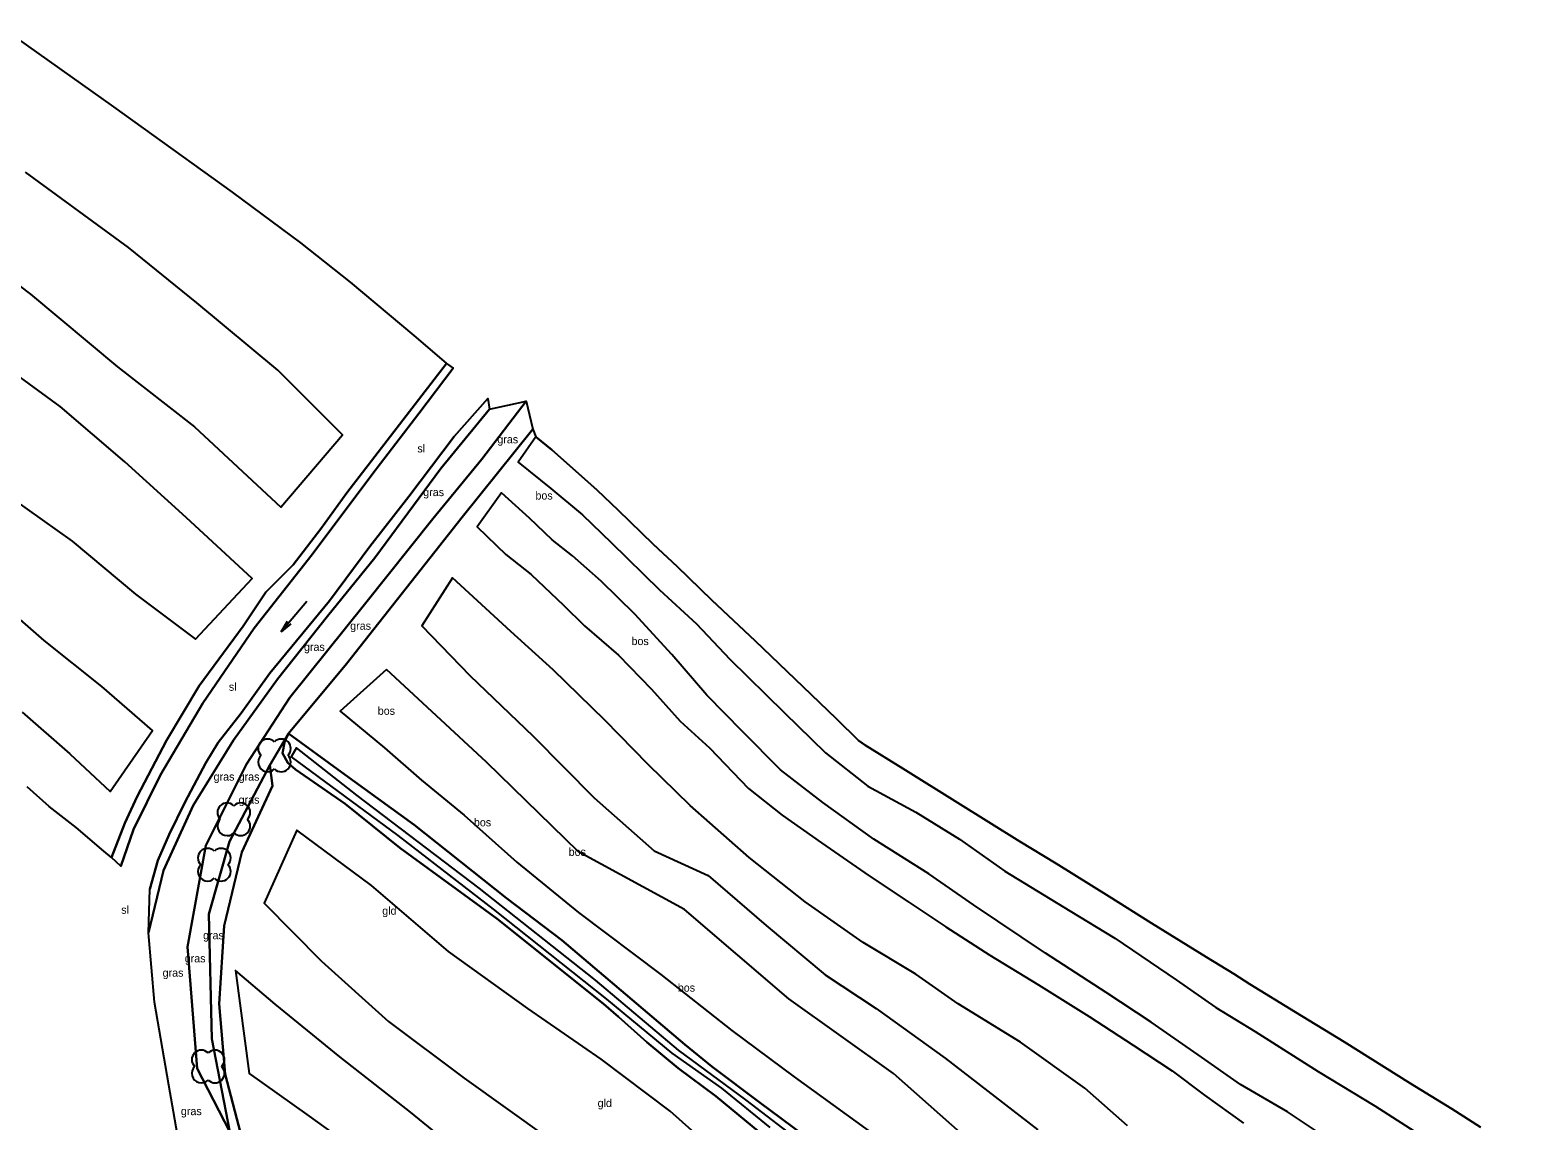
# Model space of a CAD drawing. Extents: x 154825 to 158680, y 370717 to 378075.
# Drawn here: x 155652.5 to 155841.2, y 377079.3 to 377215.8 of the extents above; entities that cross this region are included whole.
import ezdxf

# ---------------------------------------------------------------- set-up
doc = ezdxf.new("R2010")
doc.units = 0
for name, color, linetype in [('boom', 7, 'Continuous'), ('bos(vs)', 7, 'Continuous'), ('breuklijn', 7, 'Continuous'), ('grasland_productiegrasl(vs)', 7, 'Continuous'), ('grazige vegetatie(vs)', 7, 'Continuous'), ('hoogteverschillijn', 7, 'Continuous'), ('insteek sloot', 7, 'Continuous'), ('Sloot bodem', 7, 'Continuous'), ('sloot(vs)', 7, 'Continuous'), ('stroomrichting  watergangen', 7, 'Continuous'), ('vlak_Bos', 7, 'Continuous'), ('vlak_Grasland', 7, 'Continuous'), ('vlak_Grazige_vegetatie', 7, 'Continuous')]:
    doc.layers.add(name, color=color, linetype=linetype)

msp = doc.modelspace()

# ---------------------------------------------------------------- linework, layer by layer
at = {"layer": 'boom'}
for centre, start, end in [((155682.24, 377125.87), 45, 225), ((155683.93, 377125.87), 315, 135), ((155682.24, 377124.17), 134.7431, 315), ((155683.93, 377124.17), 225, 45), ((155677.15, 377117.87), 45, 225), ((155678.85, 377117.87), 315, 135), ((155677.15, 377116.17), 134.7431, 315), ((155678.85, 377116.17), 225, 45), ((155674.71, 377112.18), 45, 225), ((155676.41, 377112.18), 315, 135), ((155674.71, 377110.48), 134.7431, 315), ((155676.41, 377110.48), 225, 45), ((155673.94, 377086.92), 45, 225), ((155675.64, 377086.92), 315, 135), ((155673.94, 377085.22), 134.7431, 315), ((155675.64, 377085.22), 225, 45)]:
    msp.add_arc(centre, 1.2, start, end, dxfattribs=at)
at = {"layer": 'bos(vs)'}
msp.add_lwpolyline([(155715.41, 377165.87), (155706.56, 377154.84), (155692.09, 377136.49), (155684.83, 377127.76)], dxfattribs=at)
at = {"layer": 'breuklijn'}
for points in [[(155714.59, 377169.36), (155709.02, 377162.12), (155702.88, 377154.62), (155694.37, 377143.93), (155685.02, 377132.25), (155679.59, 377123.93), (155674.49, 377113.75), (155672.2, 377101.06), (155673.4, 377085.82), (155677.48, 377077.9), (155675.24, 377089.52), (155674.86, 377105.15), (155677.45, 377114.22), (155682.5, 377123.78), (155682.83, 377121.22), (155679.02, 377112.91), (155676.78, 377103.66), (155676.15, 377093.9), (155676.92, 377085.09), (155679.08, 377076.81), (155677.91, 377076.45), (155677.48, 377077.9)], [(155833.53, 377024.24), (155818.9, 377036.91), (155805.68, 377046.23), (155791.49, 377059.51), (155778.9, 377067.29), (155770.76, 377076.15), (155760.52, 377085.18), (155747.44, 377094.53), (155734.38, 377105.71), (155721.14, 377112.94), (155709.6, 377124.17), (155697.1, 377135.78)]]:
    msp.add_lwpolyline(points, dxfattribs=at)
at = {"layer": 'hoogteverschillijn'}
for points in [[(155649.44, 377215.82), (155662.95, 377206.22), (155677.8, 377195.53), (155686.33, 377189.18), (155692.57, 377184.26), (155700.52, 377177.59), (155703.68, 377174.88)], [(155642.36, 377190.48), (155652.55, 377182.75), (155663.43, 377173.66), (155673.07, 377166.17), (155683.88, 377156.09), (155691.59, 377165.16), (155683.5, 377173.26), (155673.39, 377181.66), (155664.84, 377188.62), (155651.94, 377198.03)], [(155646.49, 377159.86), (155657.77, 377151.84), (155665.7, 377145.19), (155673.21, 377139.57), (155680.3, 377147.18), (155672.02, 377154.79), (155664.37, 377161.78), (155656.28, 377168.7), (155646.77, 377175.61)], [(155833.99, 377078.46), (155830.39, 377080.78), (155825.24, 377083.94), (155816.92, 377089.14), (155810.84, 377092.89), (155805.14, 377096.38), (155803.12, 377097.65), (155799.69, 377099.76), (155792.8, 377104.02), (155787.53, 377107.35), (155780.9, 377111.48), (155776.35, 377114.22), (155768.57, 377119.07), (155761.69, 377123.38), (155757, 377126.28), (155756.17, 377126.9), (155753.42, 377129.58), (155750.23, 377132.65), (155743.24, 377139.35), (155737.8, 377144.46), (155733.47, 377148.66), (155730.46, 377151.47), (155726.09, 377155.72), (155723.46, 377158.24), (155721.49, 377159.97), (155717.77, 377163.27), (155715.77, 377164.92), (155713.56, 377161.74), (155717.66, 377158.43), (155721.61, 377155.14), (155725.23, 377151.67), (155731.24, 377145.76), (155735.9, 377141.51), (155740.07, 377137.08), (155746.86, 377130.4), (155752.03, 377125.32), (155757.34, 377121.15), (155763.35, 377117.93), (155768.81, 377114.52), (155774.47, 377110.52), (155782.61, 377105.57), (155788.23, 377102.13), (155795.92, 377096.91), (155800.89, 377093.47), (155805.78, 377090.47), (155813.67, 377085.46), (155820.75, 377081.15), (155831.25, 377074.41)], [(155815.73, 377076.48), (155809.85, 377080.39), (155803.94, 377083.81), (155798.65, 377087.52), (155792.77, 377091.64), (155787.15, 377095.34), (155779.55, 377100.24), (155770.55, 377106.33), (155764.96, 377110.17), (155758.09, 377114.55), (155751.7, 377119.14), (155746.42, 377123.21), (155741.65, 377128.01), (155737.17, 377132.55), (155732.8, 377137.63), (155728.18, 377142.69), (155723.96, 377146.82), (155720.36, 377149.99), (155717.82, 377152.01), (155714.99, 377154.7), (155711.48, 377157.91), (155708.44, 377153.62), (155712.02, 377150.16), (155715.2, 377147.65), (155719.24, 377143.84), (155721.87, 377141.23), (155726.14, 377137.58), (155730.28, 377133.3), (155733.84, 377129.32), (155737.5, 377125.98), (155742.41, 377120.88), (155746.61, 377117.54), (155751.51, 377114.09), (155757.51, 377109.93), (155762.44, 377106.66), (155767.08, 377103.55), (155772.6, 377100.02), (155778.68, 377096.28), (155785.02, 377092.33), (155790.54, 377088.74), (155795.4, 377085.54), (155799.45, 377082.46), (155804.35, 377078.99)], [(155789.83, 377078.64), (155784.46, 377083.35), (155776.45, 377089.11), (155768.62, 377093.93), (155763.34, 377097.63), (155756.75, 377101.6), (155749.49, 377106.7), (155742.46, 377112.22), (155735.08, 377118.75), (155729.84, 377123.88), (155724.44, 377129.41), (155717.97, 377135.73), (155712.64, 377140.53), (155705.35, 377147.23), (155701.53, 377141.26), (155707.52, 377135.02), (155715.46, 377127.42), (155723.07, 377119.71), (155730.61, 377113.09), (155737.33, 377109.97), (155744.61, 377103.72), (155751.97, 377097.55), (155758.36, 377093.33), (155767.02, 377087.11), (155778.59, 377078.15)], [(155651.5, 377130.43), (155657.47, 377125.21), (155662.52, 377120.48), (155667.82, 377128.14), (155661.5, 377133.63), (155654.29, 377139.41), (155647.2, 377145.56)], [(155697.1, 377135.78), (155691.31, 377130.54), (155696.85, 377125.96), (155701.48, 377121.9), (155706.84, 377117.55), (155713.41, 377111.67), (155721.11, 377105.34), (155731.41, 377097.58), (155740.31, 377090.57), (155748.11, 377084.79), (155759.45, 377076.54), (155772.71, 377065.49), (155781.66, 377058.32), (155788.1, 377052.22), (155797.13, 377045.23), (155804.7, 377040.21), (155814.37, 377032.18), (155822.07, 377026.41), (155831.61, 377016.98), (155841.16, 377008.6)], [(155682.5, 377123.78), (155684.83, 377127.76)], [(155661.72, 377113.02), (155658.27, 377115.99), (155654.91, 377118.61), (155652.15, 377121.07)], [(155740.69, 377073.24), (155732.59, 377080.46), (155723.95, 377086.98), (155714.79, 377093.34), (155704.87, 377100.45), (155695.24, 377108.72), (155685.89, 377115.66), (155681.78, 377106.52), (155688.95, 377099.27), (155697.36, 377091.7), (155706.8, 377084.6), (155717.38, 377077.05)], [(155706.66, 377075.01), (155700.11, 377080.37), (155691.27, 377087.26), (155683.17, 377093.89), (155678.2, 377098.09), (155679.91, 377085.2), (155687.13, 377080.04), (155694.74, 377074.61)]]:
    msp.add_lwpolyline(points, dxfattribs=at)
at = {"layer": 'insteek sloot'}
for points in [[(155704.61, 377174.07), (155692.15, 377157.89), (155688.88, 377153.4), (155685.44, 377148.89), (155682, 377145.47), (155679.15, 377141.2), (155673.66, 377133.73), (155669.56, 377126.88), (155665.91, 377119.88), (155664.37, 377116.52), (155662.69, 377112.25)], [(155671.54, 377057.59), (155672.81, 377058.51), (155673.53, 377060.04), (155673.33, 377061.8), (155672.11, 377070.82), (155669.88, 377083.72), (155668.09, 377094.12), (155667.33, 377102.79), (155669.21, 377110.61), (155672.91, 377118.73), (155677.96, 377126.92), (155683.47, 377134.58), (155689.74, 377142.43), (155695.64, 377149.76), (155703.91, 377160.95), (155709.97, 377168.36)], [(155744.79, 377077.03), (155738.29, 377082.35), (155733.6, 377085.84), (155729.67, 377089.13), (155726.11, 377092.28), (155724.25, 377093.91), (155710.93, 377104.57), (155698.78, 377113.46), (155691.94, 377118.96), (155685.73, 377123.27), (155684.76, 377124.1), (155684.1, 377125.31), (155684.4, 377126.8), (155684.83, 377127.76)], [(155684.83, 377127.76), (155691.49, 377122.9), (155700.55, 377116.34), (155712.1, 377107.15), (155719.05, 377101.88), (155734.43, 377088.82), (155737.82, 377086.08), (155743.87, 377081.52), (155753.26, 377074.56)]]:
    msp.add_lwpolyline(points, dxfattribs=at)
at = {"layer": 'Sloot bodem'}
for points in [[(155663.85, 377111.13), (155665.45, 377115.73), (155668.83, 377122.6), (155674.11, 377131.55), (155680.55, 377140.93), (155687.79, 377150.19), (155695.41, 377160.32), (155701.14, 377167.83), (155705.44, 377173.49)], [(155709.79, 377169.72), (155705.55, 377164.96), (155699.89, 377157.43), (155695.01, 377151.16), (155689.98, 377144.37), (155682.51, 377135.3), (155678.93, 377130.29), (155676.02, 377126.65), (155674.48, 377124.09), (155671.89, 377119.12), (155669.89, 377115.12), (155668.51, 377111.84), (155667.49, 377108.27)], [(155733.62, 377088.1), (155723.24, 377096.86), (155708.69, 377108.38), (155693.43, 377119.98), (155685.84, 377125.97), (155685.19, 377124.83), (155698.54, 377115), (155710.45, 377105.75), (155724.61, 377094.49), (155732.82, 377087.72), (155739, 377083.37), (155745.07, 377078.42)], [(155749.38, 377076.31), (155742.05, 377081.91), (155733.62, 377088.1)]]:
    msp.add_lwpolyline(points, dxfattribs=at)
at = {"layer": 'stroomrichting  watergangen'}
for p, q in [((155687.13, 377144.29), (155683.93, 377140.47)), ((155683.93, 377140.47), (155684.71, 377141.83)), ((155683.95, 377140.47), (155685.16, 377141.49))]:
    msp.add_line(p, q, dxfattribs=at)
at = {"layer": 'vlak_Bos'}
msp.add_lwpolyline([(155753.26, 377074.56), (155743.87, 377081.52), (155737.82, 377086.08), (155734.43, 377088.82), (155719.05, 377101.88), (155712.1, 377107.15), (155700.55, 377116.34), (155691.49, 377122.9), (155684.83, 377127.76), (155692.09, 377136.49), (155706.56, 377154.84), (155715.41, 377165.87), (155715.77, 377164.92), (155717.77, 377163.27), (155721.49, 377159.97), (155723.46, 377158.24), (155726.09, 377155.72), (155730.46, 377151.47), (155733.47, 377148.66), (155737.8, 377144.46), (155743.24, 377139.35), (155750.23, 377132.65), (155753.42, 377129.58), (155756.17, 377126.9), (155757, 377126.28), (155761.69, 377123.38), (155768.57, 377119.07), (155776.35, 377114.22), (155780.9, 377111.48), (155787.53, 377107.35), (155792.8, 377104.02), (155799.69, 377099.76), (155803.12, 377097.65), (155805.14, 377096.38), (155810.84, 377092.89), (155816.92, 377089.14), (155825.24, 377083.94), (155830.39, 377080.78), (155833.99, 377078.46)], dxfattribs=at)
at = {"layer": 'vlak_Grasland'}
for points in [[(155649.44, 377215.82), (155662.95, 377206.22), (155677.8, 377195.53), (155686.33, 377189.18), (155692.57, 377184.26), (155700.52, 377177.59), (155703.68, 377174.88), (155704.61, 377174.07), (155692.15, 377157.89), (155688.88, 377153.4), (155685.44, 377148.89), (155682, 377145.47), (155679.15, 377141.2), (155673.66, 377133.73), (155669.56, 377126.88), (155665.91, 377119.88), (155664.37, 377116.52), (155662.69, 377112.25), (155661.72, 377113.02), (155658.27, 377115.99), (155654.91, 377118.61), (155652.15, 377121.07)], [(155679.08, 377076.81), (155676.92, 377085.09), (155676.15, 377093.9), (155676.78, 377103.66), (155679.02, 377112.91), (155682.83, 377121.22), (155682.5, 377123.78), (155684.83, 377127.76), (155684.4, 377126.8), (155684.1, 377125.31), (155684.76, 377124.1), (155685.73, 377123.27), (155691.94, 377118.96), (155698.78, 377113.46), (155710.93, 377104.57), (155724.25, 377093.91), (155726.11, 377092.28), (155729.67, 377089.13), (155733.6, 377085.84), (155738.29, 377082.35), (155744.79, 377077.03)]]:
    msp.add_lwpolyline(points, dxfattribs=at)
at = {"layer": 'vlak_Grazige_vegetatie'}
for points in [[(155665.45, 377115.73), (155663.85, 377111.13), (155662.69, 377112.25), (155664.37, 377116.52), (155665.91, 377119.88), (155669.56, 377126.88), (155673.66, 377133.73), (155679.15, 377141.2), (155682, 377145.47), (155685.44, 377148.89), (155688.88, 377153.4), (155692.15, 377157.89), (155704.61, 377174.07), (155705.44, 377173.49), (155701.14, 377167.83), (155695.41, 377160.32), (155687.79, 377150.19), (155680.55, 377140.93), (155674.11, 377131.55), (155668.83, 377122.6)], [(155669.21, 377110.61), (155667.33, 377102.79), (155667.49, 377108.27), (155668.51, 377111.84), (155669.89, 377115.12), (155671.89, 377119.12), (155674.48, 377124.09), (155676.02, 377126.65), (155678.93, 377130.29), (155682.51, 377135.3), (155689.98, 377144.37), (155695.01, 377151.16), (155699.89, 377157.43), (155705.55, 377164.96), (155709.79, 377169.72), (155709.97, 377168.36), (155703.91, 377160.95), (155695.64, 377149.76), (155689.74, 377142.43), (155683.47, 377134.58), (155677.96, 377126.92), (155672.91, 377118.73)], [(155675.24, 377089.52), (155677.48, 377077.9), (155673.4, 377085.82), (155672.2, 377101.06), (155674.49, 377113.75), (155679.59, 377123.93), (155685.02, 377132.25), (155694.37, 377143.93), (155702.88, 377154.62), (155709.02, 377162.12), (155714.59, 377169.36), (155715.41, 377165.87), (155706.56, 377154.84), (155692.09, 377136.49), (155684.83, 377127.76), (155682.5, 377123.78), (155677.45, 377114.22), (155674.86, 377105.15)], [(155679.08, 377076.81), (155677.91, 377076.45), (155677.48, 377077.9), (155675.24, 377089.52), (155674.86, 377105.15), (155677.45, 377114.22), (155682.5, 377123.78), (155682.83, 377121.22), (155679.02, 377112.91), (155676.78, 377103.66), (155676.15, 377093.9), (155676.92, 377085.09)]]:
    msp.add_lwpolyline(points, close=True, dxfattribs=at)
for points in [[(155672.11, 377070.82), (155669.88, 377083.72), (155668.09, 377094.12), (155667.33, 377102.79), (155669.21, 377110.61), (155672.91, 377118.73), (155677.96, 377126.92), (155683.47, 377134.58), (155689.74, 377142.43), (155695.64, 377149.76), (155703.91, 377160.95), (155709.97, 377168.36), (155714.59, 377169.36), (155709.02, 377162.12), (155702.88, 377154.62), (155694.37, 377143.93), (155685.02, 377132.25), (155679.59, 377123.93), (155674.49, 377113.75), (155672.2, 377101.06), (155673.4, 377085.82), (155677.48, 377077.9)], [(155744.79, 377077.03), (155738.29, 377082.35), (155733.6, 377085.84), (155729.67, 377089.13), (155726.11, 377092.28), (155724.25, 377093.91), (155710.93, 377104.57), (155698.78, 377113.46), (155691.94, 377118.96), (155685.73, 377123.27), (155684.76, 377124.1), (155684.1, 377125.31), (155684.4, 377126.8), (155684.83, 377127.76), (155691.49, 377122.9), (155700.55, 377116.34), (155712.1, 377107.15), (155719.05, 377101.88), (155734.43, 377088.82), (155737.82, 377086.08), (155743.87, 377081.52), (155753.26, 377074.56)], [(155749.38, 377076.31), (155742.05, 377081.91), (155733.62, 377088.1), (155723.24, 377096.86), (155708.69, 377108.38), (155693.43, 377119.98), (155685.84, 377125.97), (155685.19, 377124.83), (155698.54, 377115), (155710.45, 377105.75), (155724.61, 377094.49), (155732.82, 377087.72), (155739, 377083.37), (155745.07, 377078.42)]]:
    msp.add_lwpolyline(points, dxfattribs=at)

# ---------------------------------------------------------------- texts
at = {"layer": 'bos(vs)'}
for p in [(155715.74, 377157.05), (155727.76, 377138.83), (155696.01, 377130.1), (155708.04, 377116.14), (155719.9, 377112.44), (155733.55, 377095.44)]:
    msp.add_text('bos', height=1, dxfattribs=at).set_placement(p)
at = {"layer": 'grasland_productiegrasl(vs)'}
for p in [(155696.57, 377105.07), (155723.52, 377081)]:
    msp.add_text('gld', height=1, dxfattribs=at).set_placement(p)
at = {"layer": 'grazige vegetatie(vs)'}
for p in [(155710.97, 377164.09), (155701.7, 377157.48), (155692.56, 377140.75), (155686.78, 377138.1), (155675.47, 377121.86), (155678.6, 377121.86), (155678.6, 377118.97), (155674.15, 377102), (155671.86, 377099.11), (155669.09, 377097.31), (155671.38, 377079.98)]:
    msp.add_text('gras', height=1, dxfattribs=at).set_placement(p)
at = {"layer": 'sloot(vs)'}
for p in [(155700.97, 377162.95), (155677.38, 377133.11), (155663.91, 377105.19)]:
    msp.add_text('sl', height=1, dxfattribs=at).set_placement(p)

doc.saveas('drawing.dxf')
